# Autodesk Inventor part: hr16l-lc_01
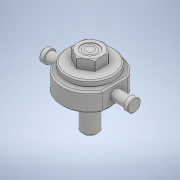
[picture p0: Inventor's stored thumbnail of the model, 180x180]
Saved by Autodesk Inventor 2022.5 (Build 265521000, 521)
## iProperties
Part Number: hr16l-lc_01
Material: 一般
Document SubType Name: Modeling
Designer: ImaoCorp
Density: 1 g/cm^3
Appearance: 既定
Author: ImaoCorp
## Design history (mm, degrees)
feature "hr16l-lc_01"
node "ソリッド1"
